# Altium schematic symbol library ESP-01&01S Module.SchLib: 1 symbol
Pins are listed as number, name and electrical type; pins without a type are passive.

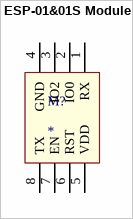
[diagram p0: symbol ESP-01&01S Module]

## ESP-01&01S Module
designator M?
footprint ESP-01&01S Module
pins: 1 RX, 2 IO0, 3 IO2, 4 GND, 5 VDD, 6 RST, 7 EN, 8 TX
